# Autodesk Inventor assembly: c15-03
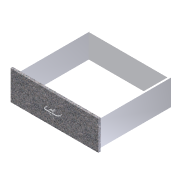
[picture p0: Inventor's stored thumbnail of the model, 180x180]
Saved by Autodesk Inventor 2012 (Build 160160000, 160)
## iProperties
Created: 2011-02
Part Number: c15-03
Document SubType Name: Assembly
Designer: Beta-8540w
Author: Beta-8540w
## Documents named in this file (12)
- C:\Users\VMuser\Desktop\Inventor 2012 Essentials\Assemblies\Chapter 15\c15-03.iam
- C:\Users\VMuser\Desktop\Inventor 2012 Essentials\Parts\Chapter 15\c15-11\c15-11-01.ipt
- C:\Inventor 2012 Essentials\Parts\Chapter 15\c15-11.ipt
- C:\Users\VMuser\Desktop\Inventor 2012 Essentials\Parts\Chapter 15\c15-12\c15-12-01.ipt
- C:\Inventor 2012 Essentials\Parts\Chapter 15\c15-12.ipt
- C:\Users\VMuser\Desktop\Inventor 2012 Essentials\Parts\Chapter 15\c15-13\c15-13-01.ipt
- C:\Inventor 2012 Essentials\Parts\Chapter 15\c15-13.ipt
- C:\Users\VMuser\Desktop\Inventor 2012 Essentials\Parts\Chapter 15\c15-15\c15-15-01.ipt
- C:\Inventor 2012 Essentials\Parts\Chapter 15\c15-15.ipt
- C:\Users\VMuser\Desktop\Inventor 2012 Essentials\Parts\Chapter 15\c15-16.ipt
- C:\Users\VMuser\Desktop\Inventor 2012 Essentials\Parts\Chapter 15\c15-17.ipt
- C:\Users\VMuser\Desktop\Inventor 2012 Essentials\Content Center Files\en-US\ANSI B18.6.3\ANSI B18.6.3 - 8-36 UNF - 0.875.ipt
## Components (9 placed, 7 different names)
1. c15-11-01:1 — Mate:1, Flush:1, Mate:2, Mate:6, Mate:7, Wire Pull Insert 1, Wire Pull Insert 2, Wire Pull Screw constraint 1, Wire Pull Screw constraint 2, Knob Insert constraint, Knob Screw constraint, Mate:10, Mate:11
2. c15-12-01:1 — Flush:2, Mate:9, Flush:4, Flush:5, Flush:6
3. c15-13-01:1 — Mate:1, Flush:1, Mate:2, Flush:2, Mate:8, Mate:9, Flush:4, Flush:5
4. c15-13-01:2 — Flush:6, Mate:10, Mate:11
5. c15-15-01:1 — Mate:6, Mate:7, Mate:8
6. c15-16:1 — Wire Pull Insert 1, Wire Pull Insert 2
7. c15-17:1 — Knob Insert constraint
8. Cross Recessed Truss Head Machine Screw - Type IA - Inch No. 8 - 36 - 7/8:1 — Wire Pull Screw constraint 1, Knob Screw constraint
9. Cross Recessed Truss Head Machine Screw - Type IA - Inch No. 8 - 36 - 7/8:2 — Wire Pull Screw constraint 2
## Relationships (19: Mate 8, Insert 6, Flush 5)
- Mate:1: c15-11-01:1 ↔ c15-13-01:1
- Flush:1: c15-11-01:1 ↔ c15-13-01:1
- Mate:2: c15-11-01:1 ↔ c15-13-01:1
- Flush:2: c15-12-01:1 ↔ c15-13-01:1
- Mate:6: c15-11-01:1 ↔ c15-15-01:1
- Mate:7: c15-11-01:1 ↔ c15-15-01:1
- Mate:8: c15-13-01:1 ↔ c15-15-01:1
- Mate:9: c15-12-01:1 ↔ c15-13-01:1
- Flush:4: c15-12-01:1 ↔ c15-13-01:1
- Flush:5: c15-12-01:1 ↔ c15-13-01:1
- Wire Pull Insert 1 [Insert]: c15-11-01:1 ↔ c15-16:1
- Wire Pull Insert 2 [Insert]: c15-11-01:1 ↔ c15-16:1
- Wire Pull Screw constraint 1 [Insert]: c15-11-01:1 ↔ Cross Recessed Truss Head Machine Screw - Type IA - Inch No. 8 - 36 - 7/8:1
- Wire Pull Screw constraint 2 [Insert]: c15-11-01:1 ↔ Cross Recessed Truss Head Machine Screw - Type IA - Inch No. 8 - 36 - 7/8:2
- Knob Insert constraint [Insert]: c15-11-01:1 ↔ c15-17:1
- Knob Screw constraint [Insert]: c15-11-01:1 ↔ Cross Recessed Truss Head Machine Screw - Type IA - Inch No. 8 - 36 - 7/8:1
- Flush:6: c15-12-01:1 ↔ c15-13-01:2
- Mate:10: c15-11-01:1 ↔ c15-13-01:2
- Mate:11: c15-11-01:1 ↔ c15-13-01:2
